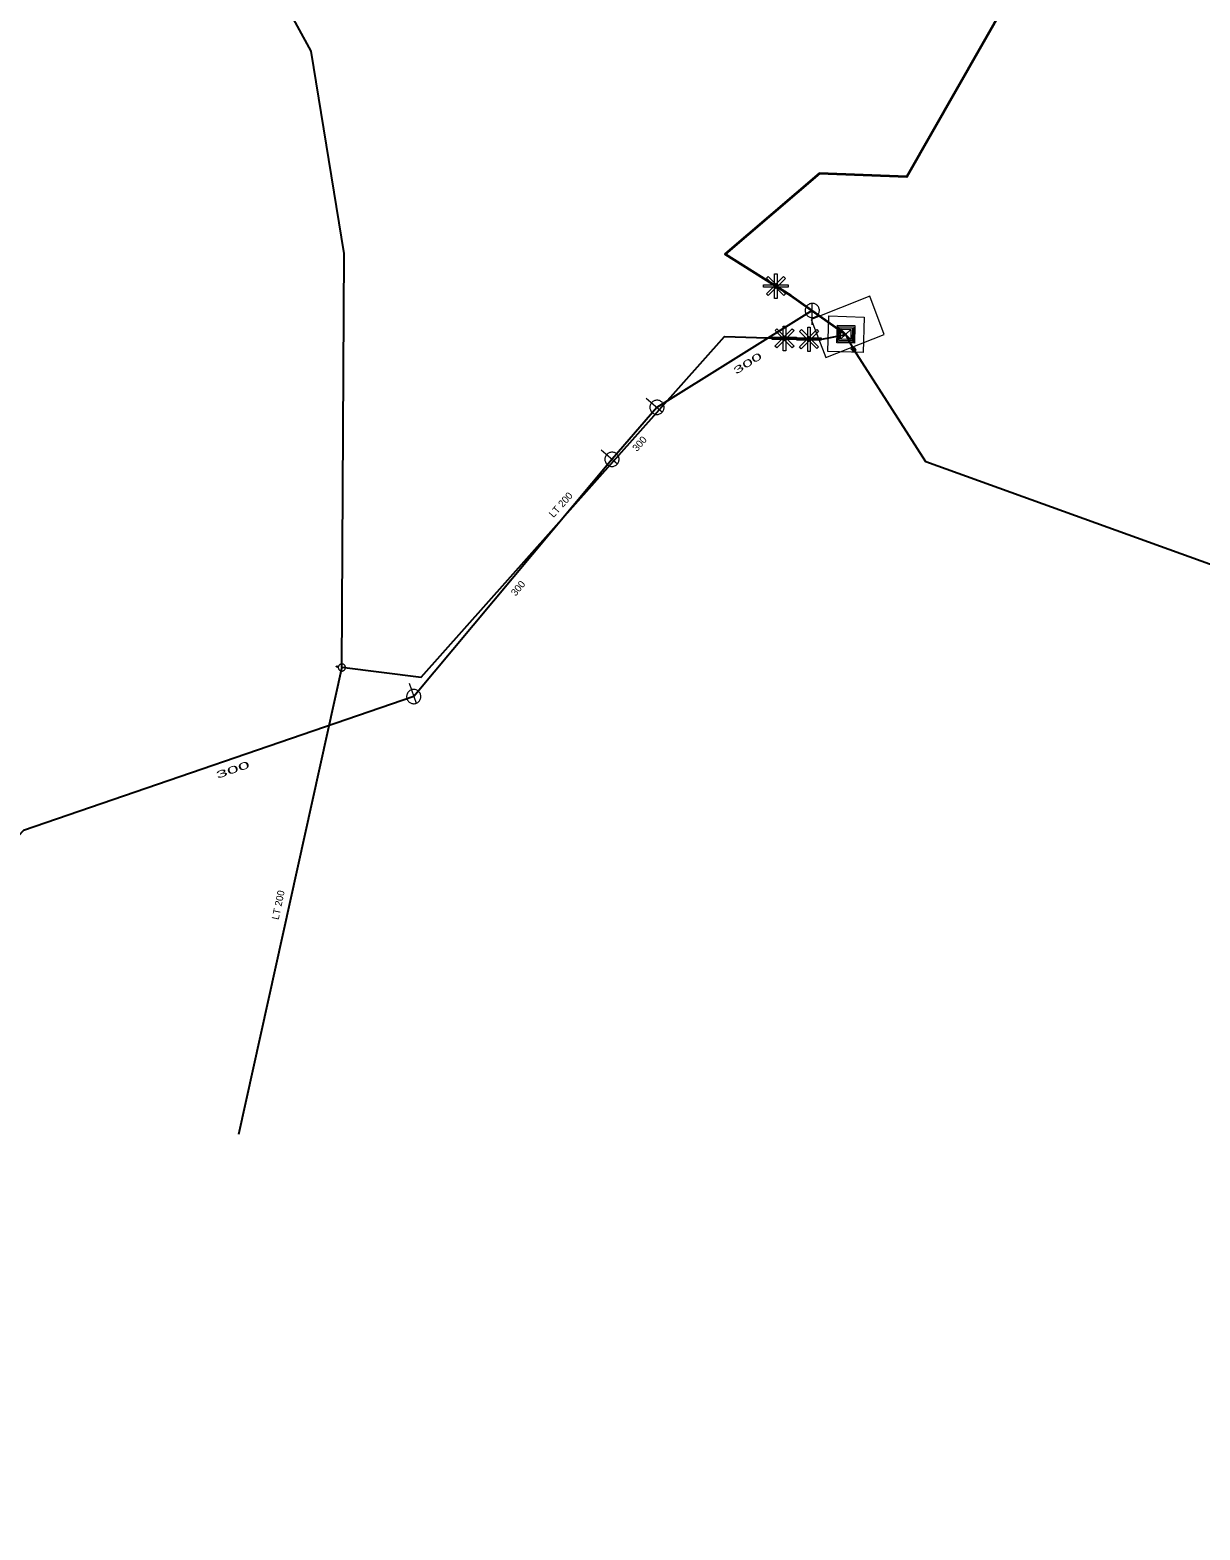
# Model space of a CAD drawing. Extents: x -809028 to -807737, y -990545 to -989489.
# Drawn here: x -808304.8 to -808140.4, y -990334.7 to -990124.1 of the extents above; entities that cross this region are included whole.
import ezdxf

# ---------------------------------------------------------------- set-up
doc = ezdxf.new("R2010")
doc.units = 0
doc.header["$LTSCALE"] = 0.32
for name, color, linetype, lineweight in [('1', 7, 'Continuous', 13), ('12', 7, 'Continuous', 13), ('14', 7, 'Continuous', 25), ('17', 7, 'Continuous', 25), ('2', 7, 'Continuous', 13), ('22', 7, 'Continuous', 13), ('23', 7, 'Continuous', 13), ('38', 7, 'Continuous', 13), ('9', 7, 'Continuous', 13)]:
    doc.layers.add(name, color=color, linetype=linetype, lineweight=lineweight)

msp = doc.modelspace()

# ---------------------------------------------------------------- linework, layer by layer
at = {"layer": '12'}
for points in [[(-808198.323, -990159.872), (-808198.323, -990160.222), (-808201.758, -990160.222), (-808201.758, -990159.872)], [(-808198.941, -990158.727), (-808198.693, -990158.975), (-808201.122, -990161.404), (-808201.369, -990161.156)], [(-808201.36, -990158.966), (-808201.113, -990158.718), (-808198.684, -990161.147), (-808198.931, -990161.395)], [(-808200.207, -990158.363), (-808199.857, -990158.363), (-808199.857, -990161.798), (-808200.207, -990161.798)], [(-808197.732, -990166.073), (-808197.483, -990166.321), (-808199.913, -990168.75), (-808200.159, -990168.502)], [(-808200.151, -990166.312), (-808199.904, -990166.064), (-808197.475, -990168.493), (-808197.722, -990168.741)], [(-808198.998, -990165.709), (-808198.647, -990165.709), (-808198.647, -990169.144), (-808198.998, -990169.144)], [(-808194.279, -990166.178), (-808194.031, -990166.426), (-808196.46, -990168.855), (-808196.706, -990168.607)], [(-808196.698, -990166.417), (-808196.451, -990166.169), (-808194.022, -990168.598), (-808194.269, -990168.846)], [(-808195.545, -990165.814), (-808195.195, -990165.814), (-808195.195, -990169.249), (-808195.545, -990169.249)], [(-808197.114, -990167.218), (-808197.114, -990167.568), (-808200.549, -990167.568), (-808200.549, -990167.218)], [(-808193.661, -990167.323), (-808193.661, -990167.673), (-808197.096, -990167.673), (-808197.096, -990167.323)]]:
    msp.add_lwpolyline(points, close=True, dxfattribs=at)
at = {"layer": '14'}
for p, q in [((-808194.918, -990163.496), (-808216.73, -990177.09)), ((-808216.73, -990177.09), (-808223.05, -990184.39)), ((-808223.05, -990184.39), (-808250.91, -990217.71))]:
    msp.add_line(p, q, dxfattribs=at)
msp.add_lwpolyline([(-808250.91, -990217.71), (-808305.724, -990236.502), (-808320.489, -990252.16)], dxfattribs=at)
at = {"layer": '17'}
for p, q in [((-808189.093, -990168.967), (-808190.203, -990166.843)), ((-808261.023, -990213.6), (-808275.539, -990279.196))]:
    msp.add_line(p, q, dxfattribs=at)
at = {"layer": '17', "lineweight": 35}
msp.add_lwpolyline([(-808175.378, -990021.169), (-808143.282, -990077.467), (-808181.622, -990144.734), (-808193.897, -990144.263), (-808207.142, -990155.57), (-808197.94, -990161.381), (-808190.203, -990166.843)], dxfattribs=at)
at = {"layer": '17'}
for points in [[(-808261.023, -990213.6), (-808260.697, -990155.498), (-808265.32, -990127.083), (-808313.08, -990039.761)], [(-808261.023, -990213.6), (-808249.853, -990214.995), (-808207.232, -990167.145), (-808193.824, -990167.546), (-808190.203, -990166.843)], [(-807903.749, -990545.399), (-807900.666, -990537.054), (-807897.291, -990527.918), (-807894.846, -990521.298), (-807895.405, -990513.283), (-807906.138, -990439.044), (-807927, -990361.261), (-807936.186, -990282.664), (-807946.574, -990253.313), (-807996.07, -990220.583), (-808011.638, -990224.296), (-808034.508, -990236.842), (-808178.98, -990184.747), (-808189.093, -990168.967)]]:
    msp.add_lwpolyline(points, dxfattribs=at)
at = {"layer": '2'}
msp.add_lwpolyline([(-808195.07, -990164.75), (-808192.989, -990170.07), (-808184.829, -990166.84), (-808186.82, -990161.5)], close=True, dxfattribs=at)
at = {"layer": '22'}
for p, q in [((-808194.918, -990165.496), (-808194.917, -990162.496)), ((-808218.242, -990175.78), (-808215.974, -990177.744)), ((-808224.562, -990183.08), (-808222.294, -990185.044)), ((-808251.558, -990215.817), (-808250.585, -990218.655))]:
    msp.add_line(p, q, dxfattribs=at)
for points in [[(-808193.918, -990163.496), (-808193.923, -990163.387), (-808193.941, -990163.279), (-808193.971, -990163.173), (-808194.011, -990163.072), (-808194.063, -990162.975), (-808194.125, -990162.885), (-808194.197, -990162.802), (-808194.277, -990162.728), (-808194.365, -990162.662), (-808194.459, -990162.607), (-808194.559, -990162.562), (-808194.664, -990162.529), (-808194.771, -990162.507), (-808194.88, -990162.497), (-808194.99, -990162.499), (-808195.098, -990162.513), (-808195.205, -990162.538), (-808195.308, -990162.575), (-808195.406, -990162.624), (-808195.498, -990162.682), (-808195.584, -990162.751), (-808195.661, -990162.828), (-808195.73, -990162.914), (-808195.789, -990163.006), (-808195.837, -990163.104), (-808195.874, -990163.207), (-808195.9, -990163.314), (-808195.914, -990163.422), (-808195.917, -990163.532), (-808195.907, -990163.641), (-808195.886, -990163.748), (-808195.852, -990163.852), (-808195.808, -990163.952), (-808195.753, -990164.047), (-808195.687, -990164.135), (-808195.613, -990164.215), (-808195.53, -990164.287), (-808195.44, -990164.349), (-808195.344, -990164.401), (-808195.242, -990164.442), (-808195.137, -990164.472), (-808195.029, -990164.49), (-808194.919, -990164.496), (-808194.81, -990164.49), (-808194.702, -990164.472), (-808194.597, -990164.443), (-808194.495, -990164.402), (-808194.398, -990164.35), (-808194.308, -990164.288), (-808194.225, -990164.217), (-808194.15, -990164.137), (-808194.085, -990164.049), (-808194.029, -990163.955), (-808193.985, -990163.855), (-808193.951, -990163.751), (-808193.929, -990163.643), (-808193.919, -990163.534)], [(-808217.384, -990177.845), (-808217.298, -990177.912), (-808217.205, -990177.969), (-808217.105, -990178.016), (-808217.002, -990178.052), (-808216.895, -990178.076), (-808216.786, -990178.088), (-808216.676, -990178.088), (-808216.568, -990178.076), (-808216.461, -990178.052), (-808216.358, -990178.017), (-808216.258, -990177.971), (-808216.164, -990177.913), (-808216.078, -990177.847), (-808215.999, -990177.771), (-808215.928, -990177.687), (-808215.868, -990177.596), (-808215.817, -990177.498), (-808215.778, -990177.396), (-808215.751, -990177.29), (-808215.734, -990177.183), (-808215.73, -990177.073), (-808215.738, -990176.964), (-808215.758, -990176.855), (-808215.789, -990176.751), (-808215.831, -990176.65), (-808215.885, -990176.555), (-808215.949, -990176.465), (-808216.021, -990176.384), (-808216.103, -990176.31), (-808216.192, -990176.247), (-808216.287, -990176.192), (-808216.388, -990176.15), (-808216.492, -990176.118), (-808216.6, -990176.097), (-808216.71, -990176.09), (-808216.819, -990176.093), (-808216.927, -990176.109), (-808217.033, -990176.136), (-808217.135, -990176.175), (-808217.233, -990176.225), (-808217.324, -990176.285), (-808217.409, -990176.355), (-808217.485, -990176.434), (-808217.552, -990176.52), (-808217.609, -990176.614), (-808217.656, -990176.712), (-808217.692, -990176.816), (-808217.716, -990176.923), (-808217.728, -990177.032), (-808217.729, -990177.141), (-808217.717, -990177.25), (-808217.693, -990177.357), (-808217.659, -990177.461), (-808217.612, -990177.56), (-808217.556, -990177.653), (-808217.488, -990177.741), (-808217.412, -990177.82)], [(-808223.704, -990185.145), (-808223.618, -990185.212), (-808223.525, -990185.269), (-808223.425, -990185.316), (-808223.322, -990185.352), (-808223.215, -990185.376), (-808223.106, -990185.388), (-808222.996, -990185.388), (-808222.888, -990185.376), (-808222.781, -990185.352), (-808222.678, -990185.317), (-808222.578, -990185.271), (-808222.484, -990185.213), (-808222.398, -990185.147), (-808222.319, -990185.071), (-808222.248, -990184.987), (-808222.188, -990184.896), (-808222.137, -990184.798), (-808222.098, -990184.696), (-808222.071, -990184.59), (-808222.054, -990184.483), (-808222.05, -990184.373), (-808222.058, -990184.264), (-808222.078, -990184.155), (-808222.109, -990184.051), (-808222.151, -990183.95), (-808222.205, -990183.855), (-808222.269, -990183.765), (-808222.341, -990183.684), (-808222.423, -990183.61), (-808222.512, -990183.547), (-808222.607, -990183.492), (-808222.708, -990183.45), (-808222.812, -990183.418), (-808222.92, -990183.397), (-808223.03, -990183.39), (-808223.139, -990183.393), (-808223.247, -990183.409), (-808223.353, -990183.436), (-808223.455, -990183.475), (-808223.553, -990183.525), (-808223.644, -990183.585), (-808223.729, -990183.655), (-808223.805, -990183.734), (-808223.872, -990183.82), (-808223.929, -990183.914), (-808223.976, -990184.012), (-808224.012, -990184.116), (-808224.036, -990184.223), (-808224.048, -990184.332), (-808224.049, -990184.441), (-808224.037, -990184.55), (-808224.013, -990184.657), (-808223.979, -990184.761), (-808223.932, -990184.86), (-808223.876, -990184.953), (-808223.808, -990185.041), (-808223.732, -990185.12)], [(-808251.856, -990218.033), (-808251.815, -990218.134), (-808251.763, -990218.231), (-808251.7, -990218.321), (-808251.629, -990218.404), (-808251.549, -990218.479), (-808251.461, -990218.544), (-808251.366, -990218.599), (-808251.266, -990218.643), (-808251.161, -990218.677), (-808251.055, -990218.699), (-808250.945, -990218.709), (-808250.835, -990218.706), (-808250.727, -990218.692), (-808250.621, -990218.666), (-808250.517, -990218.628), (-808250.42, -990218.58), (-808250.327, -990218.522), (-808250.241, -990218.453), (-808250.164, -990218.375), (-808250.096, -990218.291), (-808250.037, -990218.197), (-808249.989, -990218.1), (-808249.952, -990217.996), (-808249.926, -990217.89), (-808249.912, -990217.781), (-808249.911, -990217.672), (-808249.921, -990217.562), (-808249.943, -990217.456), (-808249.976, -990217.351), (-808250.021, -990217.251), (-808250.076, -990217.157), (-808250.142, -990217.069), (-808250.216, -990216.989), (-808250.298, -990216.917), (-808250.389, -990216.855), (-808250.485, -990216.803), (-808250.587, -990216.762), (-808250.692, -990216.733), (-808250.8, -990216.715), (-808250.91, -990216.709), (-808251.019, -990216.715), (-808251.127, -990216.733), (-808251.233, -990216.763), (-808251.334, -990216.804), (-808251.431, -990216.856), (-808251.52, -990216.917), (-808251.604, -990216.989), (-808251.679, -990217.07), (-808251.744, -990217.158), (-808251.799, -990217.252), (-808251.844, -990217.352), (-808251.877, -990217.456), (-808251.899, -990217.563), (-808251.909, -990217.672), (-808251.907, -990217.781), (-808251.893, -990217.891), (-808251.867, -990217.997)]]:
    msp.add_lwpolyline(points, close=True, dxfattribs=at)
at = {"layer": '23'}
msp.add_line((-808261.648, -990213.411), (-808261.679, -990213.605), dxfattribs=at)
for points in [[(-808261.583, -990213.62), (-808261.731, -990213.597), (-808261.864, -990213.475), (-808261.699, -990213.403), (-808261.552, -990213.427)], [(-808260.929, -990213.131), (-808260.982, -990213.126), (-808261.035, -990213.126), (-808261.086, -990213.134), (-808261.137, -990213.144), (-808261.186, -990213.161), (-808261.234, -990213.183), (-808261.279, -990213.21), (-808261.321, -990213.24), (-808261.36, -990213.276), (-808261.394, -990213.315), (-808261.426, -990213.357), (-808261.451, -990213.404), (-808261.472, -990213.451), (-808261.487, -990213.5), (-808261.498, -990213.551), (-808261.503, -990213.605), (-808261.503, -990213.656), (-808261.497, -990213.709), (-808261.486, -990213.759), (-808261.47, -990213.809), (-808261.446, -990213.857), (-808261.42, -990213.902), (-808261.389, -990213.945), (-808261.354, -990213.984), (-808261.315, -990214.017), (-808261.272, -990214.048), (-808261.227, -990214.073), (-808261.179, -990214.094), (-808261.129, -990214.109), (-808261.078, -990214.12), (-808261.026, -990214.126), (-808260.973, -990214.125), (-808260.921, -990214.119), (-808260.87, -990214.108), (-808260.822, -990214.091), (-808260.774, -990214.069), (-808260.728, -990214.043), (-808260.685, -990214.011), (-808260.647, -990213.976)], [(-808260.647, -990213.976), (-808260.613, -990213.938), (-808260.582, -990213.894), (-808260.556, -990213.85), (-808260.536, -990213.801), (-808260.521, -990213.751), (-808260.51, -990213.7), (-808260.505, -990213.649), (-808260.505, -990213.596), (-808260.511, -990213.543), (-808260.523, -990213.493), (-808260.539, -990213.443), (-808260.56, -990213.396), (-808260.588, -990213.351), (-808260.617, -990213.308), (-808260.653, -990213.27), (-808260.693, -990213.234), (-808260.735, -990213.204), (-808260.781, -990213.179), (-808260.829, -990213.159), (-808260.878, -990213.143), (-808260.929, -990213.131), (-808260.982, -990213.126), (-808261.035, -990213.126), (-808261.086, -990213.134), (-808261.137, -990213.144), (-808261.186, -990213.161), (-808261.234, -990213.183), (-808261.279, -990213.21), (-808261.321, -990213.24), (-808261.36, -990213.276), (-808261.394, -990213.315), (-808261.426, -990213.357), (-808261.451, -990213.404), (-808261.472, -990213.451), (-808261.487, -990213.5), (-808261.498, -990213.551), (-808261.503, -990213.605), (-808261.503, -990213.656), (-808261.497, -990213.709)], [(-808261.497, -990213.709), (-808261.486, -990213.759), (-808261.47, -990213.809), (-808261.446, -990213.857), (-808261.42, -990213.902), (-808261.389, -990213.945), (-808261.354, -990213.984), (-808261.315, -990214.017), (-808261.272, -990214.048), (-808261.227, -990214.073), (-808261.179, -990214.094), (-808261.129, -990214.109), (-808261.078, -990214.12), (-808261.026, -990214.126), (-808260.973, -990214.125), (-808260.921, -990214.119), (-808260.87, -990214.108), (-808260.822, -990214.091), (-808260.774, -990214.069), (-808260.728, -990214.043), (-808260.685, -990214.011), (-808260.647, -990213.976), (-808260.613, -990213.938), (-808260.582, -990213.894), (-808260.556, -990213.85), (-808260.536, -990213.801), (-808260.521, -990213.751), (-808260.51, -990213.7), (-808260.505, -990213.649), (-808260.505, -990213.596), (-808260.511, -990213.543), (-808260.523, -990213.493), (-808260.539, -990213.443), (-808260.56, -990213.396), (-808260.588, -990213.351), (-808260.617, -990213.308), (-808260.653, -990213.27), (-808260.693, -990213.234), (-808260.735, -990213.204), (-808260.781, -990213.179)], [(-808260.781, -990213.179), (-808260.829, -990213.159), (-808260.878, -990213.143), (-808260.929, -990213.131)]]:
    msp.add_lwpolyline(points, dxfattribs=at)
at = {"layer": '38'}
for p, q in [((-808190.928, -990167.515), (-808189.477, -990166.171)), ((-808190.886, -990166.129), (-808189.519, -990167.557))]:
    msp.add_line(p, q, dxfattribs=at)
for points in [[(-808192.585, -990164.256), (-808187.629, -990164.404), (-808187.778, -990169.376), (-808192.734, -990169.227)], [(-808191.384, -990165.544), (-808188.925, -990165.618), (-808188.999, -990168.087), (-808191.458, -990168.013)], [(-808191.252, -990165.732), (-808189.089, -990165.797), (-808189.153, -990167.934), (-808191.316, -990167.869)], [(-808191.08, -990165.923), (-808189.271, -990165.977), (-808189.325, -990167.763), (-808191.134, -990167.709)], [(-808190.886, -990166.129), (-808189.477, -990166.171), (-808189.519, -990167.557), (-808190.928, -990167.515)]]:
    msp.add_lwpolyline(points, close=True, dxfattribs=at)
at = {"layer": '9'}
msp.add_line((-808189.503, -990168.937), (-808188.682, -990168.996), dxfattribs=at)
for points in [[(-808189.257, -990168.778), (-808189.276, -990168.794), (-808189.293, -990168.814), (-808189.307, -990168.836), (-808189.32, -990168.861), (-808189.329, -990168.886), (-808189.335, -990168.91), (-808189.341, -990168.934), (-808189.343, -990168.961), (-808189.341, -990168.988), (-808189.338, -990169.013), (-808189.331, -990169.039), (-808189.323, -990169.063), (-808189.312, -990169.086), (-808189.298, -990169.109), (-808189.281, -990169.13), (-808189.264, -990169.148), (-808189.244, -990169.166), (-808189.223, -990169.18), (-808189.199, -990169.192), (-808189.174, -990169.203), (-808189.149, -990169.209), (-808189.125, -990169.213), (-808189.097, -990169.217), (-808189.071, -990169.215), (-808189.045, -990169.213), (-808189.021, -990169.205), (-808188.995, -990169.196), (-808188.973, -990169.186), (-808188.949, -990169.172), (-808188.929, -990169.156), (-808188.91, -990169.138), (-808188.893, -990169.118), (-808188.878, -990169.096), (-808188.865, -990169.072), (-808188.856, -990169.048), (-808188.85, -990169.023), (-808188.845, -990168.998), (-808188.844, -990168.97), (-808188.844, -990168.944), (-808188.848, -990168.918), (-808188.853, -990168.895), (-808188.862, -990168.87), (-808188.872, -990168.846), (-808188.887, -990168.822), (-808188.904, -990168.802), (-808188.921, -990168.783), (-808188.941, -990168.767), (-808188.962, -990168.752), (-808188.986, -990168.741), (-808189.01, -990168.73), (-808189.035, -990168.722), (-808189.061, -990168.718), (-808189.089, -990168.715), (-808189.115, -990168.717), (-808189.139, -990168.722), (-808189.165, -990168.727), (-808189.189, -990168.736), (-808189.213, -990168.747), (-808189.236, -990168.761)], [(-808189.503, -990168.937), (-808189.381, -990168.975), (-808189.377, -990168.914)], [(-808189.178, -990169.078), (-808189.151, -990169.084), (-808189.113, -990169.093), (-808189.089, -990169.085), (-808189.05, -990169.069), (-808188.998, -990169.024), (-808188.976, -990168.987), (-808188.965, -990168.966), (-808188.967, -990168.925), (-808188.969, -990168.897), (-808189.007, -990168.854), (-808189.033, -990168.847), (-808189.07, -990168.842), (-808189.096, -990168.849), (-808189.136, -990168.864), (-808189.189, -990168.909), (-808189.209, -990168.946), (-808189.218, -990168.971), (-808189.218, -990169.008), (-808189.215, -990169.036)]]:
    msp.add_lwpolyline(points, close=True, dxfattribs=at)

# ---------------------------------------------------------------- texts
at = {"layer": '1'}
for rotation, width, p in [(32, 2, (-808206.895, -990173.299)), (19, 2.2, (-808280.037, -990229.793))]:
    msp.add_text('  300 ', height=1, rotation=rotation, dxfattribs=dict(at, width=width)).set_placement(p)
for s, rotation, p in [('  300 ', 49, (-808220.025, -990183.929)), ('LT 200', 48, (-808231.274, -990192.654)), ('  300 ', 50, (-808237.06, -990204.24)), ('LT 200', 78, (-808269.891, -990249.114))]:
    msp.add_text(s, height=1, rotation=rotation, dxfattribs=at).set_placement(p)

doc.saveas('drawing.dxf')
